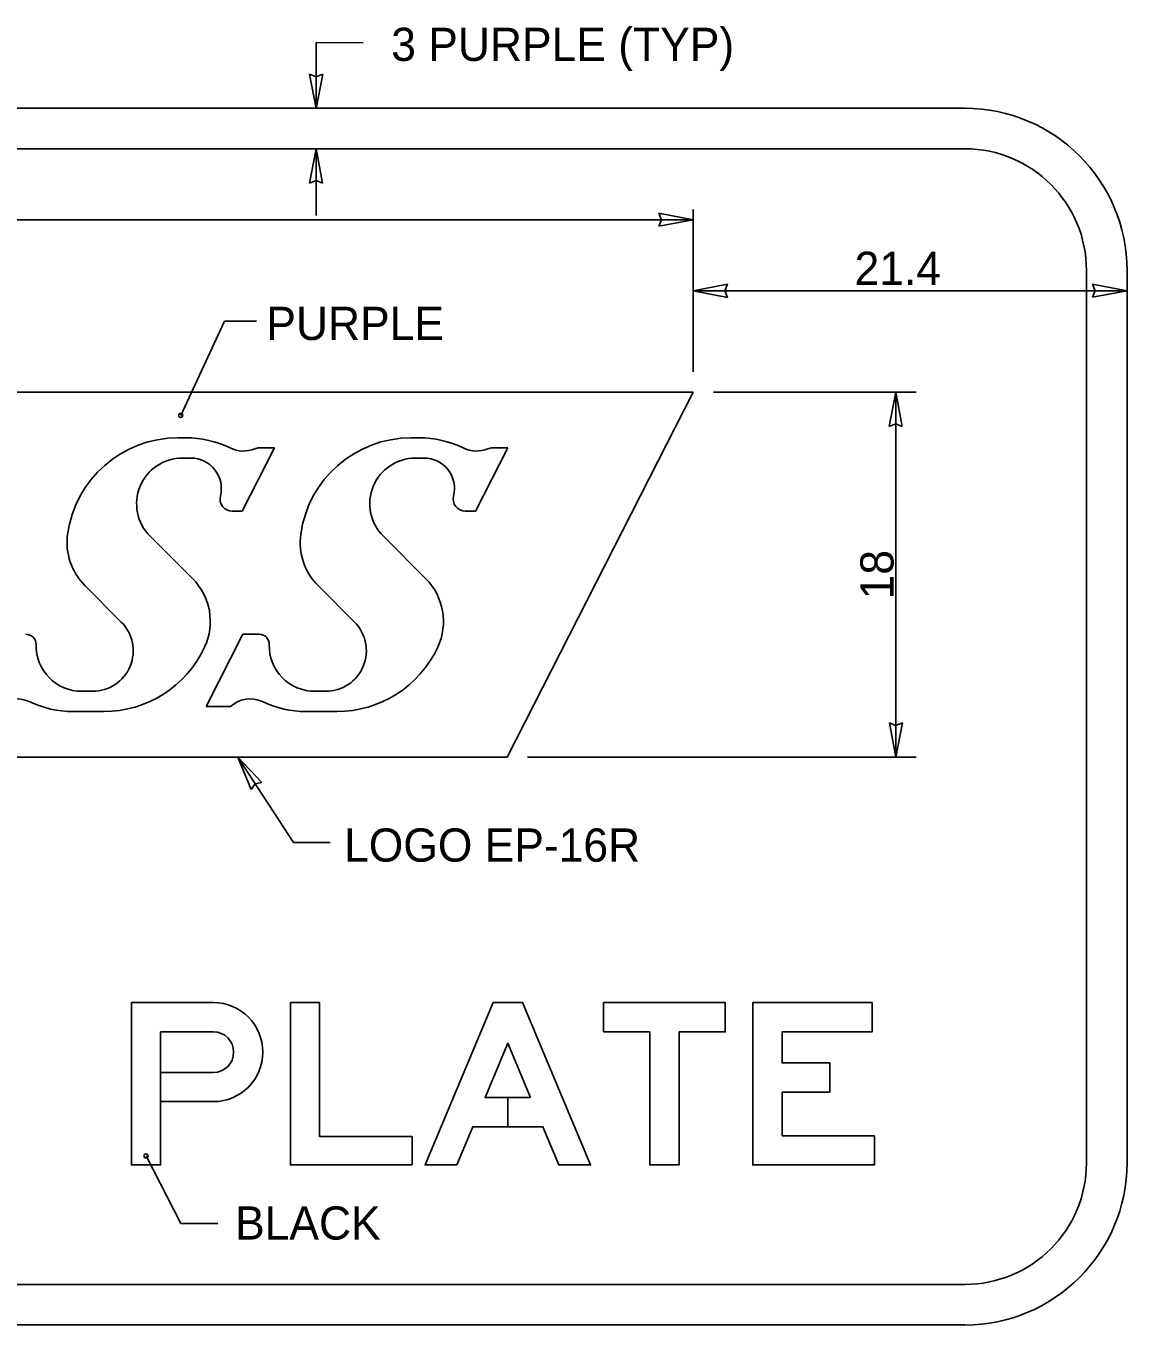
# Model space of a CAD drawing. Extents: x 319706 to 320449, y 1621775 to 1622117.
# Drawn here: x 319898.5 to 319945, y 1621859.3 to 1621914.1 of the extents above; entities that cross this region are included whole.
import ezdxf

# ---------------------------------------------------------------- set-up
doc = ezdxf.new("R2010")
doc.units = 0
for name, color, linetype in [('1', 7, 'Continuous'), ('52', 7, 'Continuous'), ('GSBWFill', 7, 'Continuous'), ('GSColorFill', 7, 'Continuous'), ('GSOutline', 7, 'Continuous'), ('SignPanel', 7, 'Continuous')]:
    doc.layers.add(name, color=color, linetype=linetype)

msp = doc.modelspace()

# ---------------------------------------------------------------- linework, layer by layer
at = {"layer": '1'}
for p, q in [((319910.75, 1621913.411), (319912.734, 1621913.398)), ((319910.75, 1621910.626), (319910.75, 1621913.411)), ((319910.75, 1621906.116), (319910.75, 1621908.929)), ((319926.653, 1621899.525), (319926.653, 1621906.365)), ((319889.548, 1621905.938), (319926.653, 1621905.938)), ((319926.653, 1621902.945), (319944.95, 1621902.945)), ((319906.886, 1621901.667), (319905.043, 1621897.689)), ((319908.244, 1621901.667), (319906.886, 1621901.667)), ((319927.508, 1621898.669), (319936.058, 1621898.669)), ((319935.203, 1621883.279), (319935.203, 1621898.669)), ((319907.448, 1621883.279), (319909.804, 1621879.681)), ((319919.666, 1621883.279), (319936.058, 1621883.279)), ((319909.804, 1621879.681), (319911.352, 1621879.681)), ((319905.054, 1621863.612), (319903.582, 1621866.466)), ((319906.616, 1621863.612), (319905.054, 1621863.612))]:
    msp.add_line(p, q, dxfattribs=at)
for centre in [(319905.043, 1621897.688), (319903.582, 1621866.466)]:
    msp.add_circle(centre, 0.0855, dxfattribs=at)
at = {"layer": '52'}
for p, q in [((319910.75, 1621911.966), (319910.48, 1621912.076)), ((319910.48, 1621912.076), (319910.75, 1621910.626)), ((319910.75, 1621910.626), (319911.03, 1621912.076)), ((319911.03, 1621912.076), (319910.75, 1621911.966)), ((319910.75, 1621908.929), (319910.47, 1621907.479)), ((319911.02, 1621907.479), (319910.75, 1621908.929)), ((319910.47, 1621907.479), (319910.75, 1621907.589)), ((319910.75, 1621907.589), (319911.02, 1621907.479)), ((319926.653, 1621905.938), (319925.203, 1621906.218)), ((319925.203, 1621906.218), (319925.313, 1621905.938)), ((319925.313, 1621905.938), (319925.203, 1621905.668)), ((319925.203, 1621905.668), (319926.653, 1621905.938)), ((319928.103, 1621903.215), (319926.653, 1621902.945)), ((319927.993, 1621902.945), (319928.103, 1621903.215)), ((319944.95, 1621902.945), (319943.5, 1621903.225)), ((319943.5, 1621903.225), (319943.61, 1621902.945)), ((319926.653, 1621902.945), (319928.103, 1621902.665)), ((319928.103, 1621902.665), (319927.993, 1621902.945)), ((319943.61, 1621902.945), (319943.5, 1621902.675)), ((319943.5, 1621902.675), (319944.95, 1621902.945)), ((319935.203, 1621898.669), (319934.923, 1621897.219)), ((319935.473, 1621897.219), (319935.203, 1621898.669)), ((319934.923, 1621897.219), (319935.203, 1621897.329)), ((319935.203, 1621897.329), (319935.473, 1621897.219)), ((319935.203, 1621884.619), (319934.933, 1621884.729)), ((319934.933, 1621884.729), (319935.203, 1621883.279)), ((319935.203, 1621883.279), (319935.483, 1621884.729)), ((319935.483, 1621884.729), (319935.203, 1621884.619)), ((319907.448, 1621883.279), (319908.008, 1621881.913)), ((319908.468, 1621882.214), (319907.448, 1621883.279)), ((319908.182, 1621882.158), (319908.468, 1621882.214)), ((319908.008, 1621881.913), (319908.182, 1621882.158))]:
    msp.add_line(p, q, dxfattribs=at)
at = {"layer": 'GSBWFill'}
msp.add_line((319904.198, 1621871.698), (319906.421, 1621871.698), dxfattribs=at)
for points in [[(319906.421, 1621872.929), (319902.966, 1621872.929), (319902.966, 1621866.088), (319904.198, 1621866.088), (319904.198, 1621871.698)], [(319906.421, 1621869.987), (319904.198, 1621869.987), (319904.198, 1621868.756), (319906.421, 1621868.756)]]:
    msp.add_lwpolyline(points, dxfattribs=at)
for points in [[(319914.802, 1621866.088), (319914.802, 1621867.285), (319910.903, 1621867.285), (319910.903, 1621872.929), (319909.671, 1621872.929), (319909.671, 1621866.088)], [(319919.8, 1621868.927), (319918.839, 1621868.927), (319918.839, 1621867.695), (319920.317, 1621867.695), (319920.992, 1621866.088), (319922.328, 1621866.088), (319919.455, 1621872.929), (319918.223, 1621872.929), (319915.35, 1621866.088), (319916.685, 1621866.088), (319917.361, 1621867.695), (319918.839, 1621867.695), (319918.839, 1621868.927), (319917.878, 1621868.927), (319918.839, 1621871.215)], [(319922.875, 1621871.698), (319924.825, 1621871.698), (319924.825, 1621866.088), (319926.057, 1621866.088), (319926.057, 1621871.698), (319928.007, 1621871.698), (319928.007, 1621872.929), (319922.875, 1621872.929)], [(319934.301, 1621867.319), (319930.401, 1621867.319), (319930.401, 1621869.159), (319932.419, 1621869.159), (319932.419, 1621870.391), (319930.401, 1621870.391), (319930.401, 1621871.698), (319934.198, 1621871.698), (319934.198, 1621872.929), (319929.17, 1621872.929), (319929.17, 1621866.088), (319934.301, 1621866.088)]]:
    msp.add_lwpolyline(points, close=True, dxfattribs=at)
for major_axis in [(0, 2.087), (0, 0.855)]:
    msp.add_ellipse((319906.421, 1621870.843), major_axis=major_axis, ratio=0.999994, start_param=3.141593, end_param=6.283185, dxfattribs=at)
at = {"layer": 'GSColorFill'}
msp.add_line((319904.198, 1621871.698), (319906.421, 1621871.698), dxfattribs=at)
for points in [[(319906.421, 1621872.929), (319902.966, 1621872.929), (319902.966, 1621866.088), (319904.198, 1621866.088), (319904.198, 1621871.698)], [(319906.421, 1621869.987), (319904.198, 1621869.987), (319904.198, 1621868.756), (319906.421, 1621868.756)]]:
    msp.add_lwpolyline(points, dxfattribs=at)
for points in [[(319914.802, 1621866.088), (319914.802, 1621867.285), (319910.903, 1621867.285), (319910.903, 1621872.929), (319909.671, 1621872.929), (319909.671, 1621866.088)], [(319919.8, 1621868.927), (319918.839, 1621868.927), (319918.839, 1621867.695), (319920.317, 1621867.695), (319920.992, 1621866.088), (319922.328, 1621866.088), (319919.455, 1621872.929), (319918.223, 1621872.929), (319915.35, 1621866.088), (319916.685, 1621866.088), (319917.361, 1621867.695), (319918.839, 1621867.695), (319918.839, 1621868.927), (319917.878, 1621868.927), (319918.839, 1621871.215)], [(319922.875, 1621871.698), (319924.825, 1621871.698), (319924.825, 1621866.088), (319926.057, 1621866.088), (319926.057, 1621871.698), (319928.007, 1621871.698), (319928.007, 1621872.929), (319922.875, 1621872.929)], [(319934.301, 1621867.319), (319930.401, 1621867.319), (319930.401, 1621869.159), (319932.419, 1621869.159), (319932.419, 1621870.391), (319930.401, 1621870.391), (319930.401, 1621871.698), (319934.198, 1621871.698), (319934.198, 1621872.929), (319929.17, 1621872.929), (319929.17, 1621866.088), (319934.301, 1621866.088)]]:
    msp.add_lwpolyline(points, close=True, dxfattribs=at)
for major_axis in [(0, 2.087), (0, 0.855)]:
    msp.add_ellipse((319906.421, 1621870.843), major_axis=major_axis, ratio=0.999994, start_param=3.141593, end_param=6.283185, dxfattribs=at)
at = {"layer": 'GSOutline'}
for p, q in [((319904.198, 1621871.698), (319906.421, 1621871.698)), ((319904.198, 1621868.756), (319906.421, 1621868.756))]:
    msp.add_line(p, q, dxfattribs=at)
for points in [[(319906.421, 1621872.929), (319902.966, 1621872.929), (319902.966, 1621866.088), (319904.198, 1621866.088), (319904.198, 1621868.756)], [(319906.421, 1621869.987), (319904.198, 1621869.987), (319904.198, 1621871.698)]]:
    msp.add_lwpolyline(points, dxfattribs=at)
for points in [[(319914.802, 1621866.088), (319914.802, 1621867.285), (319910.903, 1621867.285), (319910.903, 1621872.929), (319909.671, 1621872.929), (319909.671, 1621866.088)], [(319917.361, 1621867.695), (319920.317, 1621867.695), (319920.992, 1621866.088), (319922.328, 1621866.088), (319919.455, 1621872.929), (319918.223, 1621872.929), (319915.35, 1621866.088), (319916.685, 1621866.088)], [(319922.875, 1621871.698), (319924.825, 1621871.698), (319924.825, 1621866.088), (319926.057, 1621866.088), (319926.057, 1621871.698), (319928.007, 1621871.698), (319928.007, 1621872.929), (319922.875, 1621872.929)], [(319934.301, 1621867.319), (319930.401, 1621867.319), (319930.401, 1621869.159), (319932.419, 1621869.159), (319932.419, 1621870.391), (319930.401, 1621870.391), (319930.401, 1621871.698), (319934.198, 1621871.698), (319934.198, 1621872.929), (319929.17, 1621872.929), (319929.17, 1621866.088), (319934.301, 1621866.088)], [(319919.8, 1621868.927), (319918.839, 1621871.215), (319917.878, 1621868.927)]]:
    msp.add_lwpolyline(points, close=True, dxfattribs=at)
for major_axis in [(0, 2.087), (0, 0.855)]:
    msp.add_ellipse((319906.421, 1621870.843), major_axis=major_axis, ratio=0.999994, start_param=3.141593, end_param=6.283185, dxfattribs=at)
at = {"layer": 'SignPanel'}
for p, q in [((319828.67, 1621910.639), (319938.11, 1621910.639)), ((319828.67, 1621908.929), (319938.11, 1621908.929)), ((319943.24, 1621866.179), (319943.24, 1621903.799)), ((319944.95, 1621866.179), (319944.95, 1621903.799)), ((319877.879, 1621898.669), (319926.653, 1621898.669)), ((319918.811, 1621883.279), (319926.653, 1621898.669)), ((319904.933, 1621896.745), (319905.257, 1621896.745)), ((319914.766, 1621896.745), (319915.09, 1621896.745)), ((319905.474, 1621895.89), (319905.108, 1621895.89)), ((319909, 1621896.317), (319907.641, 1621893.651)), ((319908.359, 1621896.317), (319909, 1621896.317)), ((319915.307, 1621895.89), (319914.94, 1621895.89)), ((319918.833, 1621896.317), (319917.474, 1621893.651)), ((319918.191, 1621896.317), (319918.833, 1621896.317)), ((319907.641, 1621893.651), (319907.214, 1621893.651)), ((319917.474, 1621893.651), (319917.046, 1621893.651)), ((319903.747, 1621892.606), (319905.539, 1621890.814)), ((319913.58, 1621892.606), (319915.372, 1621890.814)), ((319902.539, 1621888.977), (319901.001, 1621890.515)), ((319912.372, 1621888.977), (319910.834, 1621890.515)), ((319906.111, 1621885.417), (319907.664, 1621888.464)), ((319907.664, 1621888.464), (319908.351, 1621888.464)), ((319900.868, 1621886.057), (319901.33, 1621886.057)), ((319910.701, 1621886.057), (319911.162, 1621886.057)), ((319901.79, 1621885.202), (319900.504, 1621885.202)), ((319907.15, 1621885.417), (319906.111, 1621885.417)), ((319911.622, 1621885.202), (319910.336, 1621885.202)), ((319876.745, 1621883.279), (319918.811, 1621883.279)), ((319828.67, 1621861.049), (319938.11, 1621861.049)), ((319828.67, 1621859.339), (319938.11, 1621859.339))]:
    msp.add_line(p, q, dxfattribs=at)
for centre, radius, start, end in [((319938.11, 1621903.798), 6.84, 0, 90), ((319938.11, 1621903.798), 5.13, 0, 90), ((319904.933, 1621892.042), 4.702, 90, 172.3089), ((319905.257, 1621892.469), 4.275, 64.0896, 90), ((319914.765, 1621892.042), 4.702, 90, 172.3089), ((319915.09, 1621892.469), 4.275, 64.0896, 90), ((319905.108, 1621893.965), 1.924, 90, 225), ((319905.474, 1621894.607), 1.282, 345.6915, 90), ((319907.685, 1621897.468), 1.282, 244.0896, 292.0347), ((319908.359, 1621895.804), 0.513, 90, 112.0347), ((319914.94, 1621893.965), 1.924, 90, 225), ((319915.307, 1621894.607), 1.282, 345.6915, 90), ((319917.518, 1621897.468), 1.282, 244.0896, 292.0347), ((319918.192, 1621895.804), 0.513, 90, 112.0347), ((319907.214, 1621894.163), 0.513, 165.6915, 270), ((319917.047, 1621894.163), 0.513, 165.6915, 270), ((319902.814, 1621892.328), 2.565, 172.3089, 225), ((319912.647, 1621892.328), 2.565, 172.3089, 225), ((319903.726, 1621888.999), 2.565, 334.95, 45), ((319913.558, 1621888.999), 2.565, 334.95, 45), ((319901.33, 1621887.767), 1.71, 270, 45), ((319911.162, 1621887.767), 1.71, 270, 45), ((319898.518, 1621888.035), 0.427, 358.6664, 90), ((319908.351, 1621888.035), 0.427, 358.6664, 90), ((319900.869, 1621887.98), 1.924, 178.6665, 270), ((319901.789, 1621889.904), 4.702, 270, 334.95), ((319910.701, 1621887.98), 1.924, 178.6665, 270), ((319911.622, 1621889.904), 4.702, 270, 334.95), ((319898.137, 1621884.543), 1.197, 64.3795, 133.1892), ((319900.503, 1621889.477), 4.275, 244.3795, 270), ((319907.969, 1621884.543), 1.197, 64.3795, 133.1892), ((319910.336, 1621889.477), 4.275, 244.3795, 270), ((319938.11, 1621866.178), 6.84, 270, 360), ((319938.11, 1621866.178), 5.13, 270, 0)]:
    msp.add_arc(centre, radius, start, end, dxfattribs=at)

# ---------------------------------------------------------------- texts
at = {"layer": '1'}
for s, p in [('3 PURPLE (TYP)', (319913.922, 1621912.632)), ('21.4', (319933.461, 1621903.19)), ('PURPLE', (319908.655, 1621900.868)), ('LOGO EP-16R', (319911.933, 1621878.874)), ('BLACK', (319907.336, 1621862.94))]:
    msp.add_text(s, height=1.4, dxfattribs=at).set_placement(p)
msp.add_text('18', height=1.4, rotation=90, dxfattribs=at).set_placement((319935.103, 1621889.931))

doc.saveas('drawing.dxf')
